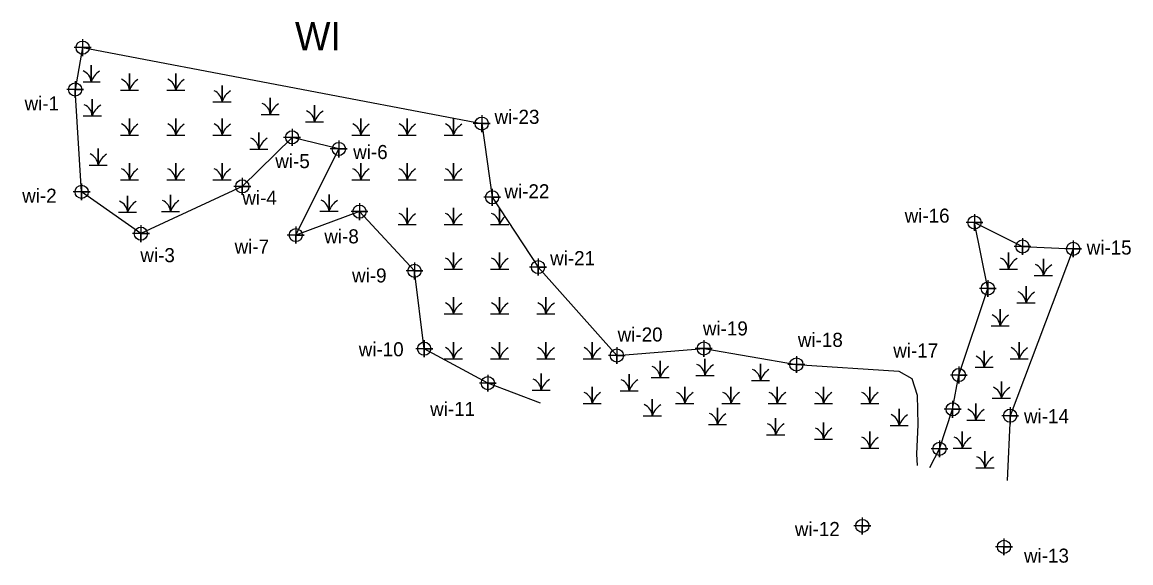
# Model space of a CAD drawing. Extents: x 2174810 to 2196950, y 76168 to 88270.
# Drawn here: x 2192008.2 to 2192402.4, y 86576.6 to 86769 of the extents above; entities that cross this region are included whole.
import ezdxf

# ---------------------------------------------------------------- set-up
doc = ezdxf.new("R2010")
doc.units = 0
for name, color, linetype in [('Exist Environmental Wetland Boundary', 7, 'Continuous'), ('Exist Environmental Wetland Boundary Cogo Point CELL', 7, 'Continuous'), ('Exist Environmental Wetland Boundary Text', 7, 'Continuous'), ('Exist Hydro Swamp or Marsh', 7, 'Continuous')]:
    doc.layers.add(name, color=color, linetype=linetype)

msp = doc.modelspace()

# ---------------------------------------------------------------- linework, layer by layer
at = {"layer": 'Exist Environmental Wetland Boundary'}
msp.add_line((2192029.7, 86759.93), (2192027.04, 86745.05), dxfattribs=at)
for points in [[(2192029.7, 86759.93), (2192171.6, 86732.9), (2192175.33, 86706.68), (2192191.64, 86681.85), (2192219.64, 86650.41), (2192250.55, 86652.89), (2192283.49, 86647.18), (2192319.94, 86644.82), (2192324.51, 86642.19), (2192326.39, 86636.29), (2192326.73, 86625.87), (2192326.21, 86615.28), (2192326.41, 86611.24)], [(2192192.49, 86633.43), (2192173.77, 86640.57), (2192151.17, 86652.81), (2192147.69, 86680.49), (2192128.17, 86701.58), (2192105.48, 86693.24), (2192120.78, 86723.88), (2192104.18, 86728.01), (2192086.48, 86710.56), (2192050.43, 86693.74), (2192029.35, 86708.6), (2192027.04, 86745.05)], [(2192330.91, 86610.49), (2192334.37, 86617.19), (2192339.06, 86631.25), (2192341.26, 86643.44), (2192351.56, 86674.22), (2192346.82, 86697.7), (2192363.89, 86689.15), (2192381.89, 86688.32), (2192359.52, 86628.97), (2192358.43, 86605.93)]]:
    msp.add_lwpolyline(points, dxfattribs=at)
at = {"layer": 'Exist Environmental Wetland Boundary Cogo Point CELL'}
for points in [[(2192029.7, 86762.93), (2192029.7, 86756.93), (2192029.7, 86759.93), (2192032.7, 86759.93), (2192026.7, 86759.93)], [(2192027.04, 86748.05), (2192027.04, 86742.05), (2192027.04, 86745.05), (2192030.04, 86745.05), (2192024.04, 86745.05)], [(2192171.6, 86735.9), (2192171.6, 86729.9), (2192171.6, 86732.9), (2192174.6, 86732.9), (2192168.6, 86732.9)], [(2192104.18, 86731.01), (2192104.18, 86725.01), (2192104.18, 86728.01), (2192107.18, 86728.01), (2192101.18, 86728.01)], [(2192120.78, 86726.88), (2192120.78, 86720.88), (2192120.78, 86723.88), (2192123.78, 86723.88), (2192117.78, 86723.88)], [(2192029.35, 86711.6), (2192029.35, 86705.6), (2192029.35, 86708.6), (2192032.35, 86708.6), (2192026.35, 86708.6)], [(2192086.48, 86713.56), (2192086.48, 86707.56), (2192086.48, 86710.56), (2192089.48, 86710.56), (2192083.48, 86710.56)], [(2192175.33, 86709.68), (2192175.33, 86703.68), (2192175.33, 86706.68), (2192178.33, 86706.68), (2192172.33, 86706.68)], [(2192128.17, 86704.58), (2192128.17, 86698.58), (2192128.17, 86701.58), (2192131.17, 86701.58), (2192125.17, 86701.58)], [(2192346.82, 86700.7), (2192346.82, 86694.7), (2192346.82, 86697.7), (2192349.82, 86697.7), (2192343.82, 86697.7)], [(2192050.43, 86696.74), (2192050.43, 86690.74), (2192050.43, 86693.74), (2192053.43, 86693.74), (2192047.43, 86693.74)], [(2192105.48, 86696.24), (2192105.48, 86690.24), (2192105.48, 86693.24), (2192108.48, 86693.24), (2192102.48, 86693.24)], [(2192363.89, 86692.15), (2192363.89, 86686.15), (2192363.89, 86689.15), (2192366.89, 86689.15), (2192360.89, 86689.15)], [(2192381.89, 86691.32), (2192381.89, 86685.32), (2192381.89, 86688.32), (2192384.89, 86688.32), (2192378.89, 86688.32)], [(2192191.64, 86684.85), (2192191.64, 86678.85), (2192191.64, 86681.85), (2192194.64, 86681.85), (2192188.64, 86681.85)], [(2192147.69, 86683.49), (2192147.69, 86677.49), (2192147.69, 86680.49), (2192150.69, 86680.49), (2192144.69, 86680.49)], [(2192351.56, 86677.22), (2192351.56, 86671.22), (2192351.56, 86674.22), (2192354.56, 86674.22), (2192348.56, 86674.22)], [(2192151.17, 86655.81), (2192151.17, 86649.81), (2192151.17, 86652.81), (2192154.17, 86652.81), (2192148.17, 86652.81)], [(2192219.64, 86653.41), (2192219.64, 86647.41), (2192219.64, 86650.41), (2192222.64, 86650.41), (2192216.64, 86650.41)], [(2192250.55, 86655.89), (2192250.55, 86649.89), (2192250.55, 86652.89), (2192253.55, 86652.89), (2192247.55, 86652.89)], [(2192283.49, 86650.18), (2192283.49, 86644.18), (2192283.49, 86647.18), (2192286.49, 86647.18), (2192280.49, 86647.18)], [(2192341.26, 86646.44), (2192341.26, 86640.44), (2192341.26, 86643.44), (2192344.26, 86643.44), (2192338.26, 86643.44)], [(2192173.77, 86643.57), (2192173.77, 86637.57), (2192173.77, 86640.57), (2192176.77, 86640.57), (2192170.77, 86640.57)], [(2192339.06, 86634.25), (2192339.06, 86628.25), (2192339.06, 86631.25), (2192342.06, 86631.25), (2192336.06, 86631.25)], [(2192359.52, 86631.97), (2192359.52, 86625.97), (2192359.52, 86628.97), (2192362.52, 86628.97), (2192356.52, 86628.97)], [(2192334.37, 86620.19), (2192334.37, 86614.19), (2192334.37, 86617.19), (2192337.37, 86617.19), (2192331.37, 86617.19)], [(2192306.94, 86592.76), (2192306.94, 86586.76), (2192306.94, 86589.76), (2192309.94, 86589.76), (2192303.94, 86589.76)], [(2192357.31, 86585.32), (2192357.31, 86579.32), (2192357.31, 86582.32), (2192360.31, 86582.32), (2192354.31, 86582.32)]]:
    msp.add_lwpolyline(points, dxfattribs=at)
for centre in [(2192029.7, 86759.93), (2192027.04, 86745.05), (2192171.6, 86732.9), (2192104.18, 86728.01), (2192120.78, 86723.88), (2192086.48, 86710.56), (2192029.35, 86708.6), (2192175.33, 86706.68), (2192128.17, 86701.58), (2192346.82, 86697.7), (2192050.43, 86693.74), (2192105.48, 86693.24), (2192363.89, 86689.15), (2192381.89, 86688.32), (2192191.64, 86681.85), (2192147.69, 86680.49), (2192351.56, 86674.22), (2192151.17, 86652.81), (2192219.64, 86650.41), (2192250.55, 86652.89), (2192283.49, 86647.18), (2192341.26, 86643.44), (2192173.77, 86640.57), (2192339.06, 86631.25), (2192359.52, 86628.97), (2192334.37, 86617.19), (2192306.94, 86589.76), (2192357.31, 86582.32)]:
    msp.add_circle(centre, 2.34, dxfattribs=at)
at = {"layer": 'Exist Hydro Swamp or Marsh'}
msp.add_line((2192115.31, 86712.93), (2192115.4, 86712.93), dxfattribs=at)
for points in [[(2192029.89, 86747.74), (2192032.75, 86747.74), (2192032.75, 86753.65), (2192032.75, 86747.74), (2192035.98, 86747.74)], [(2192043.14, 86744.76), (2192046.37, 86744.76), (2192046.37, 86750.68), (2192046.37, 86744.76), (2192049.59, 86744.76)], [(2192059.59, 86744.76), (2192062.82, 86744.76), (2192062.82, 86750.68), (2192062.82, 86744.76), (2192066.04, 86744.76)], [(2192076.04, 86740.67), (2192079.27, 86740.67), (2192079.27, 86746.4)], [(2192079.27, 86746.4), (2192079.27, 86740.67), (2192082.49, 86740.67)], [(2192029.91, 86735.68), (2192033.13, 86735.68), (2192033.13, 86741.59), (2192033.13, 86735.68), (2192036.36, 86735.68)], [(2192093.17, 86736.14), (2192096.4, 86736.14), (2192096.4, 86742.06), (2192096.4, 86736.14), (2192099.62, 86736.14)], [(2192108.95, 86733.5), (2192112.17, 86733.5), (2192112.17, 86739.41), (2192112.17, 86733.5), (2192115.4, 86733.5)], [(2192043.14, 86728.84), (2192046.37, 86728.84), (2192046.37, 86734.76), (2192046.37, 86728.84), (2192049.59, 86728.84)], [(2192059.59, 86728.84), (2192062.82, 86728.84), (2192062.82, 86734.76), (2192062.82, 86728.84), (2192066.04, 86728.84)], [(2192076.04, 86728.84), (2192079.27, 86728.84), (2192079.27, 86734.76), (2192079.27, 86728.84), (2192082.49, 86728.84)], [(2192125.4, 86728.84), (2192128.62, 86728.84), (2192128.62, 86734.76), (2192128.62, 86728.84), (2192131.85, 86728.84)], [(2192141.85, 86728.84), (2192145.07, 86728.84), (2192145.07, 86734.76), (2192145.07, 86728.84), (2192148.3, 86728.84)], [(2192158.3, 86728.84), (2192161.53, 86728.84), (2192161.53, 86734.76), (2192161.53, 86728.84), (2192164.75, 86728.84)], [(2192089.12, 86723.84), (2192092.34, 86723.84), (2192092.34, 86729.76), (2192092.34, 86723.84), (2192095.57, 86723.84)], [(2192031.99, 86718.16), (2192035.21, 86718.16), (2192035.21, 86724.08), (2192035.21, 86718.16), (2192038.44, 86718.16)], [(2192043.14, 86712.93), (2192046.37, 86712.93), (2192046.37, 86718.84), (2192046.37, 86712.93), (2192049.59, 86712.93)], [(2192059.59, 86712.93), (2192062.82, 86712.93), (2192062.82, 86718.84), (2192062.82, 86712.93), (2192066.04, 86712.93)], [(2192076.04, 86712.93), (2192079.27, 86712.93), (2192079.27, 86718.84), (2192079.27, 86712.93), (2192082.49, 86712.93)], [(2192125.4, 86712.93), (2192128.62, 86712.93), (2192128.62, 86718.84), (2192128.62, 86712.93), (2192131.85, 86712.93)], [(2192141.85, 86712.93), (2192145.07, 86712.93), (2192145.07, 86718.84), (2192145.07, 86712.93), (2192148.3, 86712.93)], [(2192158.3, 86712.93), (2192161.53, 86712.93), (2192161.53, 86718.84), (2192161.53, 86712.93), (2192164.75, 86712.93)], [(2192057.71, 86701.67), (2192060.94, 86701.67), (2192060.94, 86707.58), (2192060.94, 86701.67), (2192064.16, 86701.67)], [(2192114.08, 86701.74), (2192117.31, 86701.74), (2192117.31, 86707.66), (2192117.31, 86701.74), (2192120.53, 86701.74)], [(2192042.47, 86701.34), (2192045.7, 86701.34), (2192045.7, 86707.25), (2192045.7, 86701.34), (2192048.92, 86701.34)], [(2192141.85, 86697.01), (2192145.07, 86697.01), (2192145.07, 86702.93), (2192145.07, 86697.01), (2192148.3, 86697.01)], [(2192158.3, 86697.01), (2192161.53, 86697.01), (2192161.53, 86702.93), (2192161.53, 86697.01), (2192164.75, 86697.01)], [(2192174.75, 86697.01), (2192177.98, 86697.01), (2192177.98, 86702.65)], [(2192177.98, 86702.65), (2192177.98, 86697.01), (2192181.2, 86697.01)], [(2192158.3, 86681.09), (2192161.53, 86681.09), (2192161.53, 86687.01), (2192161.53, 86681.09), (2192164.75, 86681.09)], [(2192174.75, 86681.09), (2192177.98, 86681.09), (2192177.98, 86687.01), (2192177.98, 86681.09), (2192181.2, 86681.09)], [(2192355.71, 86681.09), (2192358.94, 86681.09), (2192358.94, 86687.01), (2192358.94, 86681.09), (2192362.17, 86681.09)], [(2192368.08, 86678.88), (2192371.3, 86678.88), (2192371.3, 86684.79), (2192371.3, 86678.88), (2192374.53, 86678.88)], [(2192361.93, 86669.12), (2192365.16, 86669.12), (2192365.16, 86675.03), (2192365.16, 86669.12), (2192368.38, 86669.12)], [(2192158.3, 86665.17), (2192161.53, 86665.17), (2192161.53, 86671.09), (2192161.53, 86665.17), (2192164.75, 86665.17)], [(2192174.75, 86665.17), (2192177.98, 86665.17), (2192177.98, 86671.09), (2192177.98, 86665.17), (2192181.2, 86665.17)], [(2192191.2, 86665.17), (2192194.43, 86665.17), (2192194.43, 86671.09), (2192194.43, 86665.17), (2192197.65, 86665.17)], [(2192375.39, 86671.09), (2192375.39, 86671.09), (2192375.39, 86671.09)], [(2192352.7, 86660.91), (2192355.93, 86660.91), (2192355.93, 86666.83), (2192355.93, 86660.91), (2192359.16, 86660.91)], [(2192158.3, 86649.26), (2192161.53, 86649.26), (2192161.53, 86655.17), (2192161.53, 86649.26), (2192164.75, 86649.26)], [(2192174.75, 86649.26), (2192177.98, 86649.26), (2192177.98, 86655.17), (2192177.98, 86649.26), (2192181.2, 86649.26)], [(2192191.2, 86649.26), (2192194.43, 86649.26), (2192194.43, 86655.17), (2192194.43, 86649.26), (2192197.65, 86649.26)], [(2192207.65, 86649.26), (2192210.88, 86649.26), (2192210.88, 86655.17), (2192210.88, 86649.26), (2192214.1, 86649.26)], [(2192359.46, 86649.26), (2192362.69, 86649.26), (2192362.69, 86655.17), (2192362.69, 86649.26), (2192365.91, 86649.26)], [(2192231.81, 86642.6), (2192235.04, 86642.6), (2192235.04, 86648.52), (2192235.04, 86642.6), (2192238.26, 86642.6)], [(2192247.76, 86643.28), (2192250.98, 86643.28), (2192250.98, 86649.2), (2192250.98, 86643.28), (2192254.21, 86643.28)], [(2192347.03, 86646.19), (2192350.26, 86646.19), (2192350.26, 86652.11), (2192350.26, 86646.19), (2192353.48, 86646.19)], [(2192267.48, 86641.52), (2192270.71, 86641.52), (2192270.71, 86647.44), (2192270.71, 86641.52), (2192273.93, 86641.52)], [(2192189.51, 86638.05), (2192192.73, 86638.05), (2192192.73, 86643.97), (2192192.73, 86638.05), (2192195.96, 86638.05)], [(2192220.84, 86637.86), (2192224.07, 86637.86), (2192224.07, 86643.77), (2192224.07, 86637.86), (2192227.29, 86637.86)], [(2192353.15, 86635.17), (2192356.37, 86635.17), (2192356.37, 86641.09), (2192356.37, 86635.17), (2192359.6, 86635.17)], [(2192207.65, 86633.34), (2192210.88, 86633.34), (2192210.88, 86639.26), (2192210.88, 86633.34), (2192214.1, 86633.34)], [(2192240.56, 86633.34), (2192243.78, 86633.34), (2192243.78, 86639.26), (2192243.78, 86633.34), (2192247.01, 86633.34)], [(2192257.01, 86633.34), (2192260.23, 86633.34), (2192260.23, 86639.26), (2192260.23, 86633.34), (2192263.46, 86633.34)], [(2192273.46, 86633.34), (2192276.68, 86633.34), (2192276.68, 86639.26), (2192276.68, 86633.34), (2192279.91, 86633.34)], [(2192289.91, 86633.34), (2192293.13, 86633.34), (2192293.13, 86639.26), (2192293.13, 86633.34), (2192296.36, 86633.34)], [(2192306.36, 86633.34), (2192309.59, 86633.34), (2192309.59, 86639.26), (2192309.59, 86633.34), (2192312.81, 86633.34)], [(2192229.03, 86628.97), (2192232.25, 86628.97), (2192232.25, 86634.89), (2192232.25, 86628.97), (2192235.48, 86628.97)], [(2192344.08, 86627.35), (2192347.3, 86627.35), (2192347.3, 86633.27), (2192347.3, 86627.35), (2192350.53, 86627.35)], [(2192252.21, 86625.84), (2192255.44, 86625.84), (2192255.44, 86631.76), (2192255.44, 86625.84), (2192258.67, 86625.84)], [(2192316.78, 86625.45), (2192320.01, 86625.45), (2192320.01, 86631.37), (2192320.01, 86625.45), (2192323.23, 86625.45)], [(2192272.89, 86622.19), (2192276.11, 86622.19), (2192276.11, 86628.11), (2192276.11, 86622.19), (2192279.34, 86622.19)], [(2192289.91, 86620.66), (2192293.13, 86620.66), (2192293.13, 86626.58), (2192293.13, 86620.66), (2192296.36, 86620.66)], [(2192306.36, 86617.42), (2192309.59, 86617.42), (2192309.59, 86623.34), (2192309.59, 86617.42), (2192312.81, 86617.42)], [(2192339.26, 86617.42), (2192342.49, 86617.42), (2192342.49, 86623.34), (2192342.49, 86617.42), (2192345.71, 86617.42)], [(2192347.31, 86610.43), (2192350.54, 86610.43), (2192350.54, 86616.35), (2192350.54, 86610.43), (2192353.77, 86610.43)]]:
    msp.add_lwpolyline(points, dxfattribs=at)
for centre, radius, start, end in [((2192028.15, 86747.4), 4.61, 4.1403, 67.535), ((2192039.59, 86745.46), 7.21, 122.1274, 161.6222), ((2192041.77, 86744.43), 4.61, 4.1403, 67.535), ((2192053.21, 86742.49), 7.21, 122.1274, 161.6222), ((2192058.22, 86744.43), 4.61, 4.1403, 67.535), ((2192069.66, 86742.49), 7.21, 122.1274, 161.6222), ((2192074.67, 86740.34), 4.61, 4.1403, 67.535), ((2192086.11, 86738.4), 7.21, 122.1274, 161.6222), ((2192028.53, 86735.34), 4.61, 4.1403, 67.535), ((2192039.97, 86733.4), 7.21, 122.1274, 161.6222), ((2192091.8, 86735.81), 4.61, 4.1403, 67.535), ((2192103.24, 86733.87), 7.21, 122.1274, 161.6222), ((2192107.57, 86733.16), 4.61, 4.1403, 67.535), ((2192119.01, 86731.22), 7.21, 122.1274, 161.6222), ((2192041.77, 86728.51), 4.61, 4.1403, 67.535), ((2192053.21, 86726.57), 7.21, 122.1274, 161.6222), ((2192058.22, 86728.51), 4.61, 4.1403, 67.535), ((2192069.66, 86726.57), 7.21, 122.1274, 161.6222), ((2192074.67, 86728.51), 4.61, 4.1403, 67.535), ((2192086.11, 86726.57), 7.21, 122.1274, 161.6222), ((2192124.02, 86728.51), 4.61, 4.1403, 67.535), ((2192135.46, 86726.57), 7.21, 122.1274, 161.6222), ((2192140.47, 86728.51), 4.61, 4.1403, 67.535), ((2192151.91, 86726.57), 7.21, 122.1274, 161.6222), ((2192156.93, 86728.51), 4.61, 4.1403, 67.535), ((2192168.37, 86726.57), 7.21, 122.1274, 161.6222), ((2192087.74, 86723.51), 4.61, 4.1403, 67.535), ((2192099.18, 86721.57), 7.21, 122.1274, 161.6222), ((2192030.61, 86717.83), 4.61, 4.1403, 67.535), ((2192042.05, 86715.89), 7.21, 122.1274, 161.6222), ((2192041.77, 86712.59), 4.61, 4.1403, 67.535), ((2192053.21, 86710.65), 7.21, 122.1274, 161.6222), ((2192058.22, 86712.59), 4.61, 4.1403, 67.535), ((2192069.66, 86710.65), 7.21, 122.1274, 161.6222), ((2192074.67, 86712.59), 4.61, 4.1403, 67.535), ((2192086.11, 86710.65), 7.21, 122.1274, 161.6222), ((2192124.02, 86712.59), 4.61, 4.1403, 67.535), ((2192135.46, 86710.65), 7.21, 122.1274, 161.6222), ((2192140.47, 86712.59), 4.61, 4.1403, 67.535), ((2192151.91, 86710.65), 7.21, 122.1274, 161.6222), ((2192156.93, 86712.59), 4.61, 4.1403, 67.535), ((2192168.37, 86710.65), 7.21, 122.1274, 161.6222), ((2192041.1, 86701), 4.61, 4.1403, 67.535), ((2192052.54, 86699.06), 7.21, 122.1274, 161.6222), ((2192056.34, 86701.33), 4.61, 4.1403, 67.535), ((2192067.78, 86699.39), 7.21, 122.1274, 161.6222), ((2192112.71, 86701.41), 4.61, 4.1403, 67.535), ((2192124.15, 86699.47), 7.21, 122.1274, 161.6222), ((2192124.02, 86696.68), 4.61, 63.6478, 67.535), ((2192140.47, 86696.68), 4.61, 4.1403, 67.535), ((2192151.91, 86694.74), 7.21, 122.1274, 161.6222), ((2192156.93, 86696.68), 4.61, 4.1403, 67.535), ((2192168.37, 86694.74), 7.21, 122.1274, 161.6222), ((2192173.38, 86696.68), 4.61, 4.1403, 67.535), ((2192184.82, 86694.74), 7.21, 134.2803, 161.6222), ((2192156.93, 86680.76), 4.61, 4.1403, 67.535), ((2192168.37, 86678.82), 7.21, 122.1274, 161.6222), ((2192173.38, 86680.76), 4.61, 4.1403, 67.535), ((2192184.82, 86678.82), 7.21, 122.1274, 161.6222), ((2192354.34, 86680.76), 4.61, 4.1403, 67.535), ((2192365.78, 86678.82), 7.21, 122.1274, 161.6222), ((2192366.7, 86678.54), 4.61, 4.1403, 67.535), ((2192378.15, 86676.6), 7.21, 122.1274, 161.6222), ((2192360.56, 86668.78), 4.61, 4.1403, 67.535), ((2192372, 86666.84), 7.21, 122.1274, 161.6222), ((2192156.93, 86664.84), 4.61, 4.1403, 67.535), ((2192168.37, 86662.9), 7.21, 122.1274, 161.6222), ((2192173.38, 86664.84), 4.61, 4.1403, 67.535), ((2192184.82, 86662.9), 7.21, 122.1274, 161.6222), ((2192189.83, 86664.84), 4.61, 4.1403, 67.535), ((2192201.27, 86662.9), 7.21, 122.1274, 161.6222), ((2192351.33, 86660.58), 4.61, 4.1403, 67.535), ((2192362.77, 86658.64), 7.21, 122.1274, 161.6222), ((2192156.93, 86648.92), 4.61, 4.1403, 67.535), ((2192168.37, 86646.98), 7.21, 122.1274, 161.6222), ((2192173.38, 86648.92), 4.61, 4.1403, 67.535), ((2192184.82, 86646.98), 7.21, 122.1274, 161.6222), ((2192189.83, 86648.92), 4.61, 4.1403, 67.535), ((2192201.27, 86646.98), 7.21, 122.1274, 161.6222), ((2192206.28, 86648.92), 4.61, 4.1403, 67.535), ((2192217.72, 86646.98), 7.21, 122.1274, 161.6222), ((2192358.09, 86648.92), 4.61, 4.1403, 67.535), ((2192369.53, 86646.98), 7.21, 122.1274, 161.6222), ((2192345.66, 86645.86), 4.61, 4.1403, 67.535), ((2192357.1, 86643.92), 7.21, 122.1274, 161.6222), ((2192230.44, 86642.27), 4.61, 4.1403, 67.535), ((2192241.88, 86640.33), 7.21, 122.1274, 161.6222), ((2192246.38, 86642.94), 4.61, 4.1403, 67.535), ((2192257.82, 86641), 7.21, 122.1274, 161.6222), ((2192266.11, 86641.19), 4.61, 4.1403, 67.535), ((2192277.55, 86639.25), 7.21, 122.1274, 161.6222), ((2192188.13, 86637.72), 4.61, 4.1403, 67.535), ((2192199.58, 86635.78), 7.21, 122.1274, 161.6222), ((2192219.47, 86637.52), 4.61, 4.1403, 67.535), ((2192230.91, 86635.58), 7.21, 122.1274, 161.6222), ((2192206.28, 86633), 4.61, 4.1403, 67.535), ((2192217.72, 86631.07), 7.21, 122.1274, 161.6222), ((2192239.18, 86633), 4.61, 4.1403, 67.535), ((2192250.62, 86631.07), 7.21, 122.1274, 161.6222), ((2192255.63, 86633), 4.61, 4.1403, 67.535), ((2192267.07, 86631.07), 7.21, 122.1274, 161.6222), ((2192272.08, 86633), 4.61, 4.1403, 67.535), ((2192283.52, 86631.07), 7.21, 122.1274, 161.6222), ((2192288.53, 86633), 4.61, 4.1403, 67.535), ((2192299.98, 86631.07), 7.21, 122.1274, 161.6222), ((2192304.99, 86633), 4.61, 4.1403, 67.535), ((2192316.43, 86631.07), 7.21, 122.1274, 161.6222), ((2192351.77, 86634.83), 4.61, 4.1403, 67.535), ((2192363.21, 86632.89), 7.21, 122.1274, 161.6222), ((2192227.65, 86628.64), 4.61, 4.1403, 67.535), ((2192239.09, 86626.7), 7.21, 122.1274, 161.6222), ((2192250.84, 86625.51), 4.61, 4.1403, 67.535), ((2192262.28, 86623.57), 7.21, 122.1274, 161.6222), ((2192315.41, 86625.12), 4.61, 4.1403, 67.535), ((2192326.85, 86623.18), 7.21, 122.1274, 161.6222), ((2192342.7, 86627.02), 4.61, 4.1403, 67.535), ((2192354.15, 86625.08), 7.21, 122.1274, 161.6222), ((2192271.51, 86621.86), 4.61, 4.1403, 67.535), ((2192282.95, 86619.92), 7.21, 122.1274, 161.6222), ((2192288.53, 86620.32), 4.61, 4.1403, 67.535), ((2192299.98, 86618.39), 7.21, 122.1274, 161.6222), ((2192304.99, 86617.09), 4.61, 4.1403, 67.535), ((2192316.43, 86615.15), 7.21, 122.1274, 161.6222), ((2192337.89, 86617.09), 4.61, 4.1403, 67.535), ((2192349.33, 86615.15), 7.21, 122.1274, 161.6222), ((2192345.94, 86610.1), 4.61, 4.1403, 67.535), ((2192357.38, 86608.16), 7.21, 122.1274, 161.6222)]:
    msp.add_arc(centre, radius, start, end, dxfattribs=at)

# ---------------------------------------------------------------- texts
at = {"layer": 'Exist Environmental Wetland Boundary Cogo Point CELL'}
for s, p in [('wi-1', (2192009.07, 86737.59)), ('wi-23', (2192176.16, 86732.81)), ('wi-6', (2192125.91, 86720.29)), ('wi-5', (2192098.21, 86717.05)), ('wi-22', (2192179.68, 86706.31)), ('wi-2', (2192008.22, 86704.75)), ('wi-4', (2192086.49, 86704.02)), ('wi-16', (2192321.99, 86697.66)), ('wi-8', (2192115.64, 86690.29)), ('wi-7', (2192083.75, 86686.64)), ('wi-15', (2192386.71, 86686.31)), ('wi-3', (2192050.23, 86683.6)), ('wi-21', (2192195.93, 86682.53)), ('wi-9', (2192125.5, 86676.37)), ('wi-20', (2192219.94, 86655.36)), ('wi-19', (2192250.24, 86657.52)), ('wi-18', (2192284.02, 86653.47)), ('wi-10', (2192127.87, 86650.11)), ('wi-17', (2192317.94, 86649.68)), ('wi-11', (2192153.26, 86628.87)), ('wi-14', (2192364.42, 86626.3)), ('wi-12', (2192282.94, 86586.16)), ('wi-13', (2192364.42, 86576.69))]:
    msp.add_text(s, height=5, dxfattribs=at).set_placement(p)
at = {"layer": 'Exist Environmental Wetland Boundary Text'}
msp.add_text('WI', height=10, dxfattribs=at).set_placement((2192105.21, 86758.99))

doc.saveas('drawing.dxf')
